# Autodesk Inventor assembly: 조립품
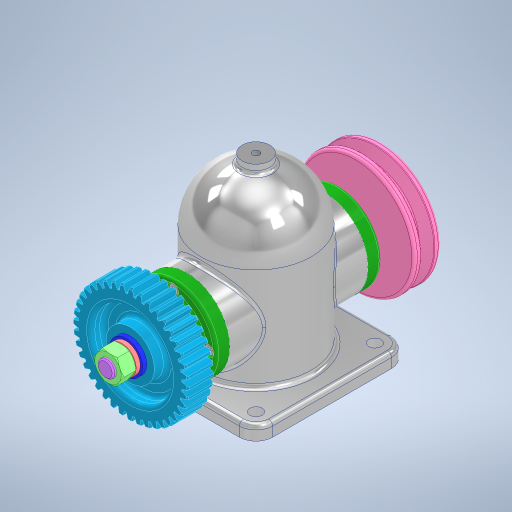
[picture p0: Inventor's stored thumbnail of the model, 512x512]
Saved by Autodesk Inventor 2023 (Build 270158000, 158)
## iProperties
Created: 2025-04
Part Number: 조립품
Document SubType Name: Assembly
Designer: User
Author: User
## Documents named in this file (14)
- C:\Users\User\Desktop\750406V1001\답안조립품.iam
- C:\Users\User\Desktop\750406V1001\본체.ipt
- C:\Users\User\Desktop\750406V1001\깊은 홈 볼 베어링 6203.ipt
- C:\Users\User\Desktop\750406V1001\축.ipt
- C:\Users\User\Desktop\750406V1001\커버.ipt
- C:\Users\User\Desktop\750406V1001\오일 실 26 38 8.ipt
- C:\Users\User\Desktop\750406V1001\6각 구멍붙이 볼트 M4x12.ipt
- C:\Users\User\Desktop\750406V1001\칼라.ipt
- C:\Users\User\Desktop\750406V1001\평행 키 5x5x12.ipt
- C:\Users\User\Desktop\750406V1001\스퍼기어.ipt
- C:\Users\User\Desktop\750406V1001\V 벨트 풀리.ipt
- C:\Users\User\Desktop\750406V1001\평와셔 M12.ipt
- C:\Users\User\Desktop\750406V1001\스프링 와셔 M12.ipt
- C:\Users\User\Desktop\750406V1001\6각 너트 M12x1.ipt
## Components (11 placed, 3 different names)
1. 6각 구멍붙이 볼트 M4x12:1
2. 6각 구멍붙이 볼트 M4x12:2
3. 6각 구멍붙이 볼트 M4x12:3
4. 6각 구멍붙이 볼트 M4x12:4
5. 6각 구멍붙이 볼트 M4x12:5
6. 6각 구멍붙이 볼트 M4x12:6
7. 6각 구멍붙이 볼트 M4x12:7
8. 6각 구멍붙이 볼트 M4x12:8
9. V 벨트 풀리:1
10. 6각 너트 M12x1:1
11. 6각 너트 M12x1:2
